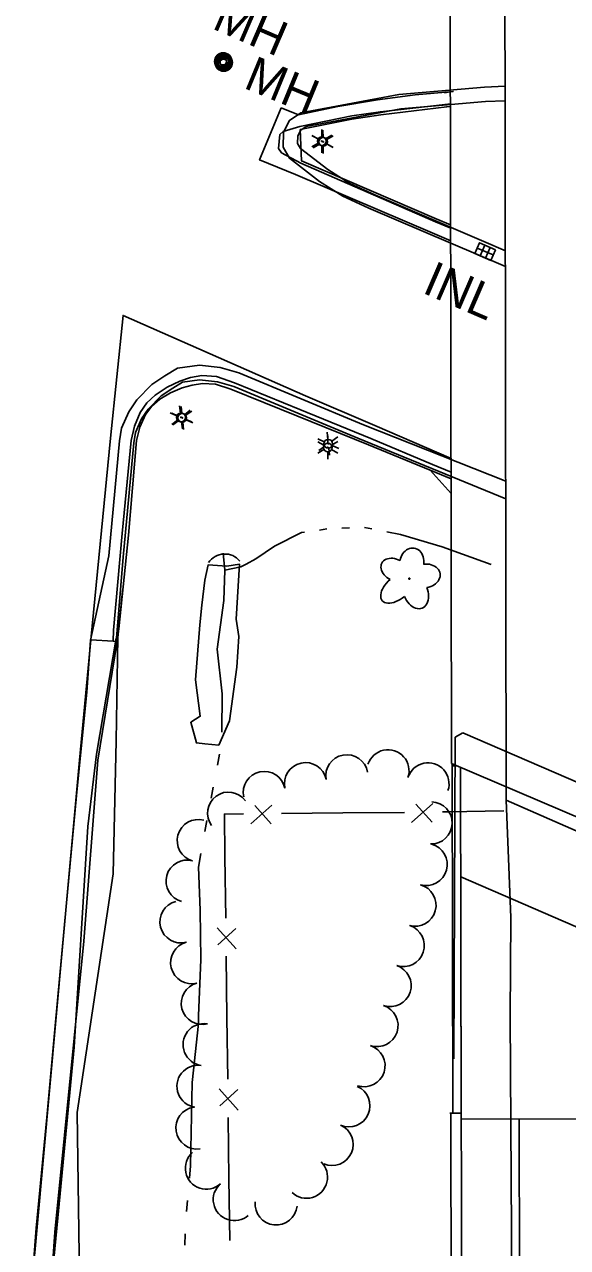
# Model space of a CAD drawing. Extents: x 588843 to 2552415, y 180129 to 269402.
# Drawn here: x 593864.4 to 593958.1, y 185348.9 to 185559.6 of the extents above; entities that cross this region are included whole.
import ezdxf

# ---------------------------------------------------------------- set-up
doc = ezdxf.new("R2010")
doc.units = 0
for name, color, linetype in [('Default', 7, 'Continuous'), ('E_DRN', 7, 'Continuous'), ('E_DRN_RipRap', 7, 'Continuous'), ('E_DRN_Text', 7, 'Continuous'), ('E_FEN_P', 7, 'Continuous'), ('E_LAND_TreeLine_P', 7, 'Continuous'), ('E_LAND_Vegetation', 7, 'Continuous'), ('E_LTG', 7, 'Continuous'), ('E_RDWY', 7, 'Continuous'), ('E_RDWY_AsphConc', 7, 'Continuous'), ('E_RDWY_BarrierConc', 7, 'Continuous'), ('E_RDWY_C_and_G', 7, 'Continuous'), ('E_RDWY_Gravel', 7, 'Continuous'), ('E_RDWY_PavtEdge', 7, 'Continuous'), ('E_STRUCT', 7, 'Continuous'), ('E_UTL_MH', 7, 'Continuous'), ('E_UTL_MH_Text', 7, 'Continuous'), ('E_WTR_P', 7, 'Continuous'), ('P_RDWY_BarrierConc', 7, 'Continuous'), ('P_RDWY_PavtEdge', 7, 'Continuous'), ('P_RDWY_ShldPaved', 7, 'Continuous'), ('P_STRUCT', 7, 'Continuous')]:
    doc.layers.add(name, color=color, linetype=linetype)

# ---------------------------------------------------------------- blocks, each defined once
blk = doc.blocks.new('LPOL')
at = {"layer": 'Default'}
for p, q in [((-4, 0), (-1.5, 0)), ((-0.75, 1.3), (-2, 3.46)), ((0.75, 1.3), (2, 3.46)), ((1.5, 0), (4, 0)), ((-2, -3.46), (-0.75, -1.3)), ((2, -3.46), (0.75, -1.3))]:
    blk.add_line(p, q, dxfattribs=at)
for radius in [1.5, 1.5, 1.5, 0.125]:
    blk.add_circle((0, 0), radius, dxfattribs=at)
blk = doc.blocks.new('MHT')
at = {"layer": 'E_UTL_MH_Text'}
blk.add_text('MH', height=12, dxfattribs=at).set_placement((-9.81, -6))
blk = doc.blocks.new('MHO')
at = {"layer": 'Default'}
for centre, radius in [((0.08, -0.12), 3), ((0.08, -0.12), 2.43), ((0.07, -0.15), 1.94), ((0.02, -0.16), 1.21)]:
    blk.add_circle(centre, radius, dxfattribs=at)
blk = doc.blocks.new('CULV2_4')
at = {"layer": 'E_DRN'}
blk.add_arc((64.6, 48.4), 80.7, 216.8699, 323.1301, dxfattribs=at)
blk = doc.blocks.new('INLO_3')
at = {"layer": 'E_DRN'}
for p, q in [((6.6, -13.1), (6.6, 0)), ((13.1, -13.1), (13.1, 0)), ((19.7, -6.6), (0, -6.6))]:
    blk.add_line(p, q, dxfattribs=at)
blk.add_lwpolyline([(0, -13.1), (19.7, -13.1), (19.7, 0), (0, 0)], close=True, dxfattribs=at)
blk = doc.blocks.new('INLT_48_2')
at = {"layer": 'E_DRN_Text'}
blk.add_text('INL', height=39.37, dxfattribs=at).set_placement((-36.2, -19.7))
blk = doc.blocks.new('MHO_3')
at = {"layer": 'E_UTL_MH'}
for centre, radius in [((0.3, -0.4), 9.84), ((0.3, -0.4), 7.98), ((0.2, -0.5), 6.35), ((0.1, -0.5), 3.97)]:
    blk.add_circle(centre, radius, dxfattribs=at)
blk = doc.blocks.new('MHT_3')
at = {"layer": 'E_UTL_MH_Text'}
blk.add_text('MH', height=39.37, dxfattribs=at).set_placement((-32.2, -19.7))
blk = doc.blocks.new('LPOL_4')
at = {"layer": 'E_LTG'}
for p, q in [((-13.1, 0), (-4.9, 0)), ((-2.5, 4.3), (-6.6, 11.4)), ((2.5, 4.3), (6.6, 11.4)), ((4.9, 0), (13.1, 0)), ((-6.6, -11.4), (-2.5, -4.3)), ((6.6, -11.4), (2.5, -4.3))]:
    blk.add_line(p, q, dxfattribs=at)
for radius in [4.92, 4.92, 4.92, 0.41]:
    blk.add_circle((0, 0), radius, dxfattribs=at)
blk = doc.blocks.new('DTRE_4')
at = {"layer": 'E_LAND_Vegetation'}
blk.add_circle((-0.6, 0), 0.601, dxfattribs=at)
for centre, major_axis, ratio in [((-6.1, 17.5), (4.5, -16.3), 0.782863), ((-19.3, 0.5), (16.2, -0.4), 0.832022), ((13.3, 9), (-17.3, -9.6), 0.691916), ((-8.2, -17.2), (5.9, 15.9), 0.716896), ((11.6, -12.2), (-16.4, 15), 0.560249)]:
    blk.add_ellipse(centre, major_axis=major_axis, ratio=ratio, start_param=1.570796, end_param=4.712389, dxfattribs=at)

msp = doc.modelspace()

# ---------------------------------------------------------------- linework, layer by layer
at = {"layer": 'E_DRN_RipRap'}
for points in [[(593894.7, 185456.13), (593895.03, 185459.52), (593895.55, 185463.87), (593896.13, 185466.52), (593899.33, 185466.24), (593901.53, 185466.6), (593900.94, 185457.15), (593901.39, 185454.17), (593901.06, 185448.88)], [(593894.7, 185456.13), (593893.91, 185446.69), (593894.76, 185440.42), (593893.12, 185439.38), (593894.1, 185435.81), (593895.53, 185435.64), (593897.93, 185435.43), (593899.79, 185439.62), (593901.06, 185448.88)]]:
    msp.add_lwpolyline(points, dxfattribs=at)
at = {"layer": 'E_FEN_P'}
for p, q in [((593907.11, 185425.11), (593903.45, 185421.86)), ((593906.97, 185421.89), (593904.16, 185425.01)), ((593934.86, 185425.38), (593931.2, 185422.13)), ((593934.73, 185422.17), (593931.92, 185425.29)), ((593897.68, 185403.97), (593900.94, 185400.32)), ((593900.9, 185403.84), (593897.78, 185401.02)), ((593898.02, 185376.21), (593901.28, 185372.56)), ((593901.24, 185376.09), (593898.13, 185373.27))]:
    msp.add_line(p, q, dxfattribs=at)
for points in [[(593947.1, 185424.11), (593937.48, 185423.93), (593936.51, 185423.92)], [(593902.19, 185423.57), (593898.92, 185423.54), (593899.01, 185416.21)], [(593919.35, 185423.75), (593908.75, 185423.64)], [(593929.95, 185423.85), (593919.35, 185423.75)], [(593899.01, 185416.21), (593899.15, 185405.62)], [(593899.23, 185399.06), (593899.36, 185388.46)], [(593899.36, 185388.46), (593899.49, 185377.86)], [(593899.57, 185371.3), (593899.7, 185360.71)], [(593899.7, 185360.71), (593899.83, 185350.11)]]:
    msp.add_lwpolyline(points, dxfattribs=at)
at = {"layer": 'E_LAND_TreeLine_P'}
for centre, start, end in [((593927.13, 185431.01), 341.8642, 161.8642), ((593920.03, 185430.14), 10.4145, 190.4145), ((593905.8, 185427.27), 12.1254, 192.1254), ((593912.89, 185428.8), 12.1254, 192.1254), ((593934.03, 185428.75), 341.8642, 161.8642), ((593899.62, 185423.71), 36.1686, 216.1686), ((593934.57, 185422.03), 268.2823, 88.2823), ((593894.4, 185418.99), 74.6652, 254.6652), ((593933.72, 185414.87), 254.5703, 74.5703), ((593892.48, 185411.99), 74.6652, 254.6652), ((593931.79, 185407.87), 254.5703, 74.5703), ((593891.43, 185404.99), 104.6713, 284.6713), ((593929.77, 185400.9), 251.7652, 71.7652), ((593893.26, 185397.96), 104.6713, 284.6713), ((593927.5, 185394.01), 251.7652, 71.7652), ((593895.1, 185390.94), 104.6713, 284.6713), ((593925.24, 185387.11), 251.9974, 71.9974), ((593895.42, 185383.84), 81.5633, 261.5633), ((593923, 185380.21), 251.9974, 71.9974), ((593894.36, 185376.66), 81.5633, 261.5633), ((593920.39, 185373.3), 246.449, 66.449), ((593894.17, 185369.48), 98.6414, 278.6414), ((593917.49, 185366.65), 246.449, 66.449), ((593895.8, 185362.56), 131.6659, 311.6659), ((593913.08, 185361), 226.4243, 46.4243), ((593900.62, 185357.14), 131.6659, 311.6659), ((593907.84, 185356.39), 174.135, 354.135)]:
    msp.add_arc(centre, 3.63, start, end, dxfattribs=at)
at = {"layer": 'E_RDWY'}
msp.add_lwpolyline([(593875.84, 185453.5), (593875.18, 185444.55), (593873.42, 185426.77), (593871.63, 185407.61), (593869.74, 185387.1), (593868.31, 185371.28), (593866.46, 185352.19), (593864.94, 185332.65), (593864.52, 185319.97), (593864.65, 185298.49), (593864.53, 185275.87), (593864.59, 185257.56), (593864.77, 185235.68), (593864.91, 185217.64), (593865.21, 185192.03), (593865.51, 185169.15)], dxfattribs=at)
at = {"layer": 'E_RDWY_AsphConc'}
msp.add_lwpolyline([(593880.44, 185453.26), (593877.09, 185432.82), (593874.68, 185401.65), (593869.68, 185351.53), (593868.04, 185328.52), (593868.59, 185305.06), (593869.44, 185252.63), (593869.98, 185207.15), (593870.24, 185177.47), (593870.68, 185147.16), (593871.02, 185130.16)], dxfattribs=at)
at = {"layer": 'E_RDWY_BarrierConc'}
msp.add_lwpolyline([(593937.96, 185372.16), (593938.03, 185339.45), (593938.08, 185303.3), (593938.5, 185252.99), (593938.55, 185202.16), (593938.47, 185154.12), (593938.23, 185123.59), (593938.78, 185094.92), (593938.68, 185047.47)], dxfattribs=at)
at = {"layer": 'E_RDWY_C_and_G'}
for points in [[(593947.32, 185548.95), (593943.77, 185548.78), (593929.01, 185547.53), (593912.07, 185544.37), (593910.16, 185543.07), (593909.12, 185541.01), (593909.03, 185538.45), (593910.14, 185536.55), (593915.3, 185532.53), (593919.37, 185529.99), (593923.83, 185527.93), (593942.69, 185519.89), (593947.37, 185517.87)], [(593908.71, 185545.25), (593911.68, 185544), (593918.48, 185545.45), (593925.32, 185546.62), (593925.32, 185546.62), (593931.84, 185547.46), (593938.38, 185548.05), (593938.38, 185548.05)], [(593947.33, 185546.45), (593943.94, 185546.29), (593929.34, 185545.05), (593913.04, 185542.01), (593912.1, 185541.36), (593911.6, 185540.38), (593911.55, 185539.09), (593912.06, 185538.23), (593916.73, 185534.58), (593920.56, 185532.19), (593924.84, 185530.22), (593943.67, 185522.19), (593947.37, 185520.59)], [(593937.94, 185522.33), (593934.76, 185523.67), (593911.2, 185533.72), (593904.97, 185536.24), (593908.71, 185545.25)], [(593909.05, 185541.12), (593911.91, 185541.99), (593920.89, 185543.82), (593920.89, 185543.82), (593925.82, 185544.56), (593925.82, 185544.56), (593936.97, 185545.81), (593936.97, 185545.81), (593937.89, 185545.9)], [(593911.97, 185541.48), (593920.89, 185543.25), (593920.89, 185543.25), (593925.9, 185544.02), (593925.9, 185544.02), (593937.27, 185545.41), (593937.27, 185545.41), (593937.89, 185545.47)], [(593937.94, 185524.48), (593935.31, 185525.6), (593912.1, 185535.69), (593908.78, 185537.49), (593908.24, 185538.22), (593908.45, 185540.62), (593909.05, 185541.12)], [(593937.93, 185525.08), (593935.45, 185526.12), (593912.2, 185536.12), (593911.97, 185541.48)], [(593912.9, 185495.63), (593881.44, 185509.47), (593879.25, 185488.31), (593877.69, 185472.43), (593875.85, 185453.59), (593879.72, 185453.36), (593880.44, 185453.26)], [(593947.44, 185480.9), (593922.91, 185490.61), (593901.39, 185499.57), (593898.19, 185500.47), (593894.6, 185500.89), (593890.83, 185500.38), (593888.65, 185499.03), (593886.42, 185497.56), (593883.79, 185494.9), (593882.42, 185492.84), (593881.18, 185490.03), (593880.84, 185487.83), (593878.97, 185468.06), (593875.84, 185453.5)], [(593911.95, 185493.24), (593900.64, 185497.85), (593897.57, 185498.95), (593897.57, 185498.95), (593895.05, 185499.11), (593895.05, 185499.11), (593893.09, 185498.78), (593891.21, 185498.16), (593891.21, 185498.16), (593889.03, 185497.09), (593886.99, 185495.75), (593886.99, 185495.75), (593885.53, 185494.39), (593884.4, 185492.73), (593884.4, 185492.73), (593883.41, 185490.4), (593882.84, 185487.93), (593882.84, 185487.93), (593881.26, 185471.87), (593879.79, 185455.22), (593879.72, 185453.36)], [(593947.44, 185477.89), (593921.95, 185488.3), (593900.57, 185497.21), (593897.7, 185498.01), (593894.62, 185498.37), (593891.69, 185497.98), (593890, 185496.92), (593888.02, 185495.62), (593885.74, 185493.31), (593884.62, 185491.63), (593883.6, 185489.32), (593883.32, 185487.52), (593881.46, 185467.84), (593880.32, 185453.86)], [(593911.43, 185492.17), (593900.05, 185496.73), (593897.36, 185497.59), (593897.36, 185497.59), (593895.15, 185497.73), (593895.15, 185497.73), (593893.36, 185497.47), (593891.62, 185496.96), (593891.62, 185496.96), (593889.63, 185496.1), (593887.75, 185495.01), (593887.75, 185495.01), (593886.37, 185493.84), (593885.29, 185492.37), (593885.29, 185492.37), (593884.32, 185490.21), (593883.74, 185487.9), (593883.74, 185487.9), (593882.37, 185471.62), (593880.72, 185455.47), (593880.44, 185453.26)], [(593938.01, 185484.79), (593924.88, 185490.47), (593912.9, 185495.63)], [(593938.01, 185481.31), (593934.38, 185482.78), (593923.76, 185487.14), (593911.43, 185492.17)], [(593938.01, 185482.43), (593934.78, 185483.77), (593924.17, 185488.23), (593911.95, 185493.24)], [(593881.33, 185461.99), (593880.83, 185456.74), (593880.55, 185453.99)]]:
    msp.add_lwpolyline(points, dxfattribs=at)
at = {"layer": 'E_RDWY_Gravel'}
for points in [[(593938.02, 185478.81), (593934.38, 185482.78)], [(593868.28, 185183.24), (593868.29, 185205.46), (593868.14, 185229.51), (593868.36, 185257.81), (593867.92, 185280.99), (593867.98, 185300.88), (593867.76, 185329.05), (593870.2, 185354), (593873.03, 185383.38), (593875.37, 185421.39), (593876.83, 185433.85), (593880.22, 185453.87)], [(593880.55, 185453.99), (593880.27, 185436.18), (593879.73, 185413.27), (593873.51, 185372.17), (593873.98, 185339.4), (593872.71, 185305.48), (593873.23, 185253.41), (593874.93, 185203.22), (593876.95, 185154.58), (593875.43, 185130.24)]]:
    msp.add_lwpolyline(points, dxfattribs=at)
at = {"layer": 'E_RDWY_PavtEdge'}
msp.add_lwpolyline([(593875.85, 185453.59), (593873.92, 185432.86), (593870.99, 185400.68), (593866.59, 185351.79), (593864.42, 185328.6), (593864.71, 185305.3), (593865.19, 185252.78), (593865.69, 185207.57), (593865.81, 185180.99), (593866.2, 185154.42), (593866.2, 185154.42), (593866.82, 185130.11), (593866.82, 185130.11)], dxfattribs=at)
at = {"layer": 'E_STRUCT'}
for points in [[(593947.53, 185425.93), (594007.57, 185399.67), (594069.43, 185373.6), (594069.03, 185595.2), (594007.48, 185621.74), (593947.15, 185647.44), (593947.53, 185425.93)], [(593938.1, 185432.27), (594092.05, 185366.69), (594091.65, 185474.37), (594091.41, 185581.17), (593937.6, 185645.83)], [(593937.6, 185645.83), (593937.74, 185594.93), (593937.91, 185537.56), (593938.1, 185432.27)], [(593940.03, 185437.58), (593938.7, 185436.78), (593938.47, 185381.39)], [(593940.03, 185437.58), (594091.04, 185372.39), (594091.42, 185371.08), (594091.82, 185162.88), (594092.22, 184996.64), (594092.65, 184834.31), (594092.95, 184677.06)], [(593947.53, 185425.93), (593947.89, 185415.89)], [(593949.5, 184809.8), (593949.49, 184844.07), (593949.38, 184874.99), (593949.34, 184910.76), (593949.25, 184952.33), (593949.24, 184977.34), (593949.2, 185005.39), (593949.13, 185032.79), (593948.99, 185077.15), (593948.89, 185110.83), (593948.85, 185154.41), (593949.04, 185179.37), (593949.06, 185215.53), (593948.81, 185257.23), (593948.62, 185298.71), (593948.49, 185342.33), (593948.21, 185388.66), (593948.33, 185405.71), (593947.89, 185415.89)]]:
    msp.add_lwpolyline(points, dxfattribs=at)
at = {"layer": 'E_WTR_P'}
for points in [[(593916.6, 185472.67), (593915.31, 185472.49)], [(593920.49, 185472.89), (593919.19, 185472.82)], [(593924.37, 185472.69), (593923.09, 185472.94)], [(593912.73, 185472.14), (593912.21, 185472.07), (593907.57, 185469.7), (593904.32, 185467.54), (593902.66, 185466.6), (593901.76, 185466.15), (593898.98, 185465.58), (593898.72, 185468.52)], [(593944.9, 185466.53), (593936.45, 185469.58), (593929.31, 185471.74), (593926.92, 185472.2)], [(593898.98, 185465.58), (593898.81, 185460.34), (593897.67, 185451.96), (593898.53, 185444.29), (593898.47, 185437.69)], [(593898.05, 185433.87), (593897.7, 185431.97)], [(593896.98, 185428.17), (593896.63, 185426.27)], [(593895.91, 185422.47), (593895.55, 185420.57)], [(593894.86, 185416.77), (593894.43, 185414.43), (593894.71, 185407.03), (593894.85, 185398.49), (593894.47, 185388.81)], [(593894.47, 185388.81), (593894.42, 185387.46), (593893.33, 185377.34), (593893.07, 185362.94), (593892.89, 185360.86)], [(593892.56, 185357.01), (593892.4, 185355.09)], [(593892.15, 185351.23), (593892.09, 185349.3)]]:
    msp.add_lwpolyline(points, dxfattribs=at)
at = {"layer": 'P_RDWY_BarrierConc'}
for p, q in [((593941.13, 184768.81), (593939.74, 185387.02)), ((593939.77, 185372.02), (593937.77, 185372.01))]:
    msp.add_line(p, q, dxfattribs=at)
at = {"layer": 'P_RDWY_PavtEdge'}
msp.add_line((593939.78, 185371.01), (594011.77, 185371.17), dxfattribs=at)
msp.add_lwpolyline([(593937.88, 185547.98), (593936.88, 185547.83)], dxfattribs=at)
at = {"layer": 'P_RDWY_ShldPaved'}
msp.add_line((593951.77, 184483.94), (593949.78, 185371.03), dxfattribs=at)
at = {"layer": 'P_STRUCT'}
for p, q in [((593938.19, 185431.88), (593938.19, 185432.23)), ((593938.32, 185372.02), (593938.19, 185431.88)), ((593939, 185431.88), (593938.19, 185431.88)), ((593939.77, 185372.02), (593939.64, 185431.61)), ((593939.68, 185412.74), (594013.2, 185380.99))]:
    msp.add_line(p, q, dxfattribs=at)

# ---------------------------------------------------------------- block references
at = {"layer": 'E_DRN'}
for name, p, xscale, yscale, rotation in [('INLO_3', (593944.87, 185518.95), 0.1524003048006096, 0.15240030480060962, 156.65618338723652), ('CULV2_4', (593901.58, 185467.14), 0.041831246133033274, 0.041831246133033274, -177.2133558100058)]:
    msp.add_blockref(name, p, dxfattribs=dict(at, xscale=xscale, yscale=yscale, rotation=rotation))
at = {"layer": 'E_DRN_Text', "xscale": 0.1524003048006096, "yscale": 0.15240030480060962, "rotation": -23.343816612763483}
msp.add_blockref('INLT_48_2', (593939.09, 185514.02), dxfattribs=at)
at = {"layer": 'E_LAND_Vegetation', "xscale": 0.1524003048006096, "yscale": 0.1524003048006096, "rotation": -97.36026881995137}
msp.add_blockref('DTRE_4', (593930.8, 185464.02), dxfattribs=at)
at = {"layer": 'E_LTG'}
for name, p, xscale, yscale, rotation in [('LPOL', (593915.72, 185539.49), 0.5000000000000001, 0.5, -89.67337617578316), ('LPOL_4', (593915.94, 185539.37), 0.1524003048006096, 0.1524003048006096, -89.2544447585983), ('LPOL', (593891.43, 185491.9), 0.49999999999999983, 0.49999999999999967, -22.215816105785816), ('LPOL_4', (593891.65, 185491.81), 0.1524003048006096, 0.15240030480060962, -84.36014555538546), ('LPOL_4', (593916.83, 185487.36), 0.1524003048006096, 0.15240030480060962, -84.36014555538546), ('LPOL', (593916.74, 185486.72), 0.5000000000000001, 0.5, -89.67337617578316)]:
    msp.add_blockref(name, p, dxfattribs=dict(at, xscale=xscale, yscale=yscale, rotation=rotation))
at = {"layer": 'E_UTL_MH'}
for name, p, xscale, yscale, rotation in [('MHO', (593898.7, 185553.29), 0.49999999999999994, 0.5000000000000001, -23.33669759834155), ('MHO_3', (593898.78, 185553.09), 0.15240030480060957, 0.15240030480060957, -22.40034978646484)]:
    msp.add_blockref(name, p, dxfattribs=dict(at, xscale=xscale, yscale=yscale, rotation=rotation))
at = {"layer": 'E_UTL_MH_Text'}
for name, p, xscale, yscale, rotation in [('MHT', (593902.28, 185559.76), 0.49999999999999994, 0.5000000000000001, -23.33669759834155), ('MHT_3', (593907.7, 185549.63), 0.15240030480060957, 0.15240030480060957, -22.40034978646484)]:
    msp.add_blockref(name, p, dxfattribs=dict(at, xscale=xscale, yscale=yscale, rotation=rotation))

doc.saveas('drawing.dxf')
